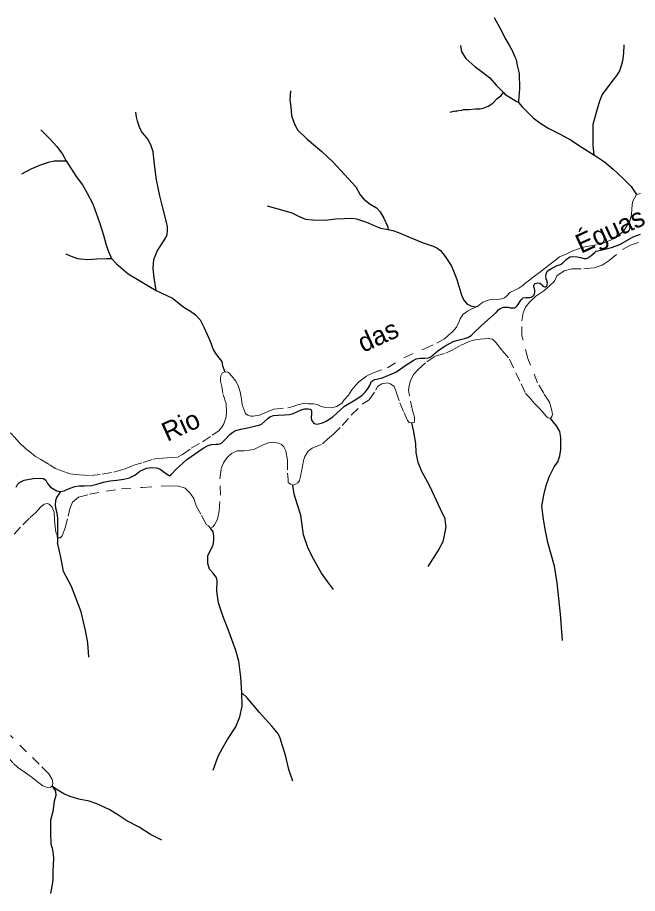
# Model space of a CAD drawing. Extents: x 391.8 to 446, y 8452 to 8507.5.
# Drawn here: x 398.8 to 405.31, y 8490.84 to 8500.03 of the extents above; entities that cross this region are included whole.
import ezdxf
from ezdxf.enums import TextEntityAlignment as Align

# ---------------------------------------------------------------- set-up
doc = ezdxf.new("R2010")
doc.units = 0
doc.header["$LTSCALE"] = 0.064
doc.linetypes.add('LONG_DASHED', pattern=[7.5, 6, -1.5])
doc.linetypes.add('SHORT_DASHED', pattern=[2.7, 1.5, -1.2])
for name, color, linetype, lineweight in [('21', 7, 'SHORT_DASHED', 13), ('7', 7, 'Continuous', 25), ('9', 7, 'LONG_DASHED', 25)]:
    doc.layers.add(name, color=color, linetype=linetype, lineweight=lineweight)
doc.layers.add('61', color=7, linetype='Continuous')

msp = doc.modelspace()

# ---------------------------------------------------------------- linework, layer by layer
at = {"layer": '21'}
for points in [[(405.2964, 8498.1764), (405.3393, 8498.1894)], [(405.2249, 8497.8981), (405.2433, 8497.9719), (405.247, 8498.0198), (405.2507, 8498.0714), (405.2581, 8498.1083), (405.2729, 8498.1378), (405.2964, 8498.1764)], [(403.6289, 8497.0059), (403.6827, 8497.0475), (403.7393, 8497.067), (403.7873, 8497.078), (403.8353, 8497.0744), (403.8796, 8497.0817), (403.9091, 8497.0928), (403.9313, 8497.1112), (403.9645, 8497.1481), (404.0199, 8497.1739), (404.0605, 8497.196), (404.1011, 8497.2218), (404.1233, 8497.244), (404.1602, 8497.2698), (404.2119, 8497.3103), (404.2783, 8497.3583), (404.3411, 8497.4062), (404.3891, 8497.4468), (404.4481, 8497.491), (404.4888, 8497.5242), (404.5515, 8497.5463), (404.6106, 8497.5795), (404.7191, 8497.6216), (404.7744, 8497.6327), (404.8889, 8497.6511), (404.9849, 8497.6806), (405.0809, 8497.7248), (405.1252, 8497.7617), (405.1658, 8497.8023), (405.1916, 8497.8428), (405.2249, 8497.8981)], [(404.3943, 8495.8284), (404.3998, 8495.8383), (404.4088, 8495.8534), (404.4149, 8495.8685), (404.4058, 8495.9107), (404.3817, 8495.9981), (404.3213, 8496.0915), (404.2579, 8496.2), (404.1564, 8496.4554), (404.0921, 8496.693), (404.0921, 8496.8535), (404.1049, 8496.9369), (404.1306, 8496.9947), (404.1756, 8497.0525), (404.2399, 8497.1103), (404.3235, 8497.1681), (404.3813, 8497.2194), (404.4351, 8497.2677), (404.4608, 8497.3255), (404.5379, 8497.3769), (404.6151, 8497.3961), (404.7436, 8497.3961), (404.8529, 8497.409), (404.9365, 8497.4347), (405.0072, 8497.486), (405.1486, 8497.6016), (405.2322, 8497.6465), (405.3157, 8497.6722)], [(400.973, 8496.3154), (401.0059, 8496.3122), (401.0244, 8496.2975), (401.0429, 8496.2754), (401.0909, 8496.2201), (401.113, 8496.1721), (401.1352, 8496.1058), (401.1499, 8496.0283), (401.1573, 8495.9693), (401.1758, 8495.914), (401.1905, 8495.8808), (401.2164, 8495.8624), (401.2459, 8495.8513), (401.2718, 8495.8513), (401.3382, 8495.8624), (401.3936, 8495.8882), (401.4896, 8495.9251), (401.6336, 8495.9398), (401.691, 8495.9545), (401.7464, 8495.9729), (401.7981, 8495.984), (401.8498, 8495.9803), (401.9052, 8495.9803), (401.9421, 8495.9729), (401.979, 8495.9582), (402.0122, 8495.9471), (402.0787, 8495.9398), (402.1082, 8495.9435), (402.1488, 8495.9545), (402.2042, 8495.9914), (402.2264, 8496.0246), (402.2707, 8496.0725), (402.3076, 8496.1278), (402.3408, 8496.1684), (402.3814, 8496.2126), (402.4663, 8496.2753), (402.5254, 8496.3011), (402.6805, 8496.3601), (402.8594, 8496.4686), (403.0699, 8496.5571), (403.1991, 8496.6161), (403.2803, 8496.664), (403.3172, 8496.6972), (403.3689, 8496.7414), (403.4059, 8496.7857), (403.4317, 8496.8373), (403.4428, 8496.8742), (403.4723, 8496.9184), (403.5203, 8496.9516), (403.5609, 8496.9737), (403.6289, 8497.0059)], [(402.9374, 8495.7801), (402.961, 8495.785), (402.9662, 8495.8008), (402.9662, 8495.8404), (402.9425, 8495.9117), (402.9134, 8496.0621), (402.9028, 8496.1228), (402.9081, 8496.1703), (402.9213, 8496.2152), (402.9543, 8496.2885), (403.0057, 8496.3463), (403.0957, 8496.4233), (403.1857, 8496.4811), (403.295, 8496.5132), (403.3592, 8496.5453), (403.4557, 8496.5967), (403.5392, 8496.6352), (403.5842, 8496.648), (403.6549, 8496.6609), (403.7385, 8496.6673), (403.7835, 8496.6609), (403.8221, 8496.6224), (403.8864, 8496.5389), (403.9635, 8496.449), (404.0278, 8496.3078), (404.0856, 8496.1922), (404.1306, 8496.0895), (404.1756, 8496.0446), (404.2206, 8495.9868), (404.2656, 8495.9418), (404.3171, 8495.8905), (404.3424, 8495.8534), (404.3605, 8495.8383), (404.3943, 8495.8284)], [(400.7391, 8495.5808), (400.8425, 8495.6509), (400.9126, 8495.6988), (400.9422, 8495.7357), (400.9643, 8495.7725), (400.9865, 8495.8463), (400.9901, 8495.8979), (400.9865, 8495.9827), (400.9532, 8496.0896), (400.9432, 8496.1611), (400.9284, 8496.2201), (400.9284, 8496.2532), (400.9321, 8496.2754), (400.9469, 8496.3012), (400.973, 8496.3154)], [(401.6869, 8495.1278), (401.7157, 8495.1373), (401.74, 8495.1534), (401.7588, 8495.1776), (401.7696, 8495.218), (401.7777, 8495.2745), (401.7885, 8495.3229), (401.7992, 8495.3848), (401.8127, 8495.4279), (401.8504, 8495.4844), (401.8908, 8495.5167), (401.9996, 8495.5602), (402.051, 8495.6116), (402.1153, 8495.6629), (402.2053, 8495.7528), (402.3017, 8495.862), (402.4174, 8495.9775), (402.4881, 8496.0225), (402.5588, 8496.1252), (402.5781, 8496.1637), (402.6231, 8496.1894), (402.681, 8496.2022), (402.7131, 8496.1894), (402.7517, 8496.1637), (402.771, 8496.1059), (402.8095, 8495.9904), (402.8579, 8495.8853), (402.8922, 8495.8061), (402.9081, 8495.785), (402.9374, 8495.7801)], [(398.658, 8495.6998), (398.681, 8495.6905), (398.7032, 8495.6868), (398.7327, 8495.6647), (398.7659, 8495.6315), (398.8176, 8495.5725), (398.8804, 8495.5135), (398.9431, 8495.4619), (398.9874, 8495.4287), (399.0428, 8495.3955), (399.1351, 8495.3402), (399.1942, 8495.3033), (399.2533, 8495.2812), (399.3456, 8495.248), (399.4526, 8495.237), (399.5671, 8495.2296), (399.6869, 8495.2416), (399.8087, 8495.2637), (399.9084, 8495.2932), (400.0081, 8495.3338), (400.1152, 8495.3669), (400.2222, 8495.4001), (400.2665, 8495.4075)], [(400.2665, 8495.4075), (400.3219, 8495.4112), (400.4142, 8495.4186), (400.477, 8495.4223), (400.5287, 8495.4481), (400.621, 8495.5144), (400.7391, 8495.5808)], [(400.8231, 8494.6778), (400.8479, 8494.6912), (400.8649, 8494.7116), (400.8956, 8494.7695), (400.9127, 8494.8581), (400.9297, 8495.0215), (400.9229, 8495.1952), (400.9365, 8495.3042), (400.9604, 8495.3621), (400.9979, 8495.4166), (401.0423, 8495.4609), (401.1036, 8495.4881), (401.1767, 8495.4896), (401.2282, 8495.496), (401.2796, 8495.5024), (401.3696, 8495.5474), (401.4274, 8495.5731), (401.4724, 8495.5795), (401.5367, 8495.5666)], [(401.5367, 8495.5666), (401.5689, 8495.5538), (401.5946, 8495.5281), (401.6139, 8495.4896), (401.6331, 8495.3869), (401.6331, 8495.2521), (401.6376, 8495.1857)], [(401.6376, 8495.1857), (401.6403, 8495.1534), (401.6484, 8495.148), (401.6618, 8495.1373), (401.6726, 8495.1346), (401.6869, 8495.1278)], [(399.2168, 8494.5807), (399.2261, 8494.576), (399.2454, 8494.576), (399.2647, 8494.5953), (399.2968, 8494.6787), (399.3291, 8494.801), (399.3483, 8494.8781), (399.3741, 8494.9487), (399.4383, 8495.0001), (399.554, 8495.0322), (399.7276, 8495.0643), (399.8883, 8495.0899), (400.1069, 8495.1028), (400.4026, 8495.122), (400.4926, 8495.1156), (400.5569, 8495.0964), (400.6083, 8495.045), (400.6469, 8494.9872), (400.6726, 8494.9102), (400.7285, 8494.8104), (400.7626, 8494.7457), (400.7763, 8494.715), (400.8035, 8494.7014), (400.8231, 8494.6778)], [(398.7627, 8494.6121), (398.8532, 8494.711), (398.9303, 8494.788), (398.9946, 8494.8458), (399.0396, 8494.8971), (399.0782, 8494.9292), (399.1103, 8494.9357), (399.1296, 8494.9292), (399.1617, 8494.8971), (399.181, 8494.8458), (399.1874, 8494.7623), (399.1939, 8494.6917), (399.2004, 8494.6338), (399.2133, 8494.6017), (399.2133, 8494.5824), (399.2168, 8494.5807)], [(398.5354, 8492.5364), (398.5676, 8492.4593), (398.6254, 8492.363), (398.6833, 8492.2924), (398.754, 8492.209), (398.799, 8492.1704), (398.8674, 8492.1185), (398.9498, 8492.0613), (399.0071, 8492.0148), (399.0644, 8491.9719), (399.1109, 8491.954), (399.1431, 8491.9576), (399.1605, 8491.9698)], [(399.1605, 8491.9698), (399.1682, 8492.0005), (399.1611, 8492.0398), (399.1252, 8492.1006), (399.025, 8492.2007), (398.8925, 8492.3295), (398.7242, 8492.5011)]]:
    msp.add_lwpolyline(points, dxfattribs=at)
at = {"layer": '7'}
for points in [[(403.9478, 8496.9943), (403.9694, 8496.9871), (404.0006, 8496.9895), (404.015, 8496.9895), (404.0294, 8496.9943), (404.0438, 8497.0086), (404.0702, 8497.0494), (404.0846, 8497.0709), (404.1062, 8497.0925), (404.1326, 8497.0973), (404.1782, 8497.0973), (404.1902, 8497.0997), (404.1998, 8497.1069), (404.2118, 8497.1141), (404.2214, 8497.1261), (404.2286, 8497.1476), (404.2286, 8497.174), (404.2262, 8497.1884), (404.2166, 8497.21), (404.2166, 8497.2219), (404.2214, 8497.2339), (404.231, 8497.2435), (404.2454, 8497.2483), (404.2598, 8497.2507), (404.2814, 8497.2483), (404.2958, 8497.2363), (404.3054, 8497.2243), (404.3126, 8497.2147), (404.3294, 8497.2076), (404.3414, 8497.2076), (404.3534, 8497.2171), (404.3582, 8497.2291), (404.3606, 8497.2507), (404.3558, 8497.2747), (404.3486, 8497.2938), (404.3438, 8497.3202), (404.3462, 8497.3418), (404.3534, 8497.3609), (404.363, 8497.3753), (404.4038, 8497.4017), (404.4623, 8497.4321), (404.4983, 8497.4441), (404.5175, 8497.4561), (404.5367, 8497.4728), (404.5559, 8497.4944), (404.5943, 8497.5232), (404.6231, 8497.5256), (404.6711, 8497.5232), (404.7071, 8497.516), (404.7455, 8497.5064), (404.7719, 8497.5064), (404.7863, 8497.5112), (404.8151, 8497.5328), (404.8583, 8497.5687), (404.8733, 8497.5812), (404.8901, 8497.586), (404.9621, 8497.6028), (405.0341, 8497.6195), (405.1205, 8497.6531), (405.2596, 8497.7322), (405.3364, 8497.7609)], [(403.6036, 8496.7393), (403.7044, 8496.8351), (403.822, 8496.9406), (403.847, 8496.9679), (403.8638, 8496.9823), (403.8998, 8496.9943), (403.9478, 8496.9943)], [(399.2486, 8495.0603), (399.2871, 8495.0667), (399.3341, 8495.0884), (399.3991, 8495.1136), (399.4461, 8495.1209), (399.5003, 8495.1209), (399.5726, 8495.1245), (399.6304, 8495.1389), (399.6991, 8495.1606), (399.7714, 8495.1714), (399.8401, 8495.1786), (399.9123, 8495.1894), (399.9738, 8495.2039), (400.028, 8495.2328), (400.0822, 8495.2761), (400.1509, 8495.3049), (400.2087, 8495.3122), (400.2529, 8495.3086), (400.2709, 8495.305), (400.2962, 8495.2941), (400.336, 8495.2653), (400.3721, 8495.24), (400.3902, 8495.2292), (400.4046, 8495.2292), (400.4155, 8495.2436), (400.4589, 8495.2905), (400.5745, 8495.3952), (400.748, 8495.5143), (400.7996, 8495.5444), (400.8337, 8495.5553), (400.8817, 8495.5577), (400.9033, 8495.5577), (400.9225, 8495.5601), (400.9392, 8495.5697), (400.9752, 8495.6032), (401.028, 8495.6583), (401.0592, 8495.6847), (401.0904, 8495.7015), (401.1432, 8495.7159), (401.2296, 8495.7326), (401.2992, 8495.7494), (401.3352, 8495.7566), (401.3592, 8495.7686), (401.3904, 8495.7973), (401.424, 8495.8285), (401.4456, 8495.8429), (401.484, 8495.8597), (401.5344, 8495.8621), (401.5992, 8495.8668), (401.6496, 8495.8692), (401.6832, 8495.8764), (401.7312, 8495.898), (401.7743, 8495.9172), (401.8127, 8495.9292), (401.8487, 8495.9268), (401.8703, 8495.9244), (401.8799, 8495.9172), (401.8847, 8495.9004), (401.8847, 8495.8764), (401.8799, 8495.8381), (401.8839, 8495.8097), (401.8935, 8495.7953), (401.9055, 8495.7809), (401.9151, 8495.7737), (401.9319, 8495.7689), (401.9583, 8495.7713), (401.9991, 8495.7833), (402.0375, 8495.7977), (402.1071, 8495.8456), (402.2318, 8495.9559), (402.359, 8496.035), (402.4166, 8496.0709), (402.4478, 8496.1021), (402.4718, 8496.1356), (402.4958, 8496.174), (402.511, 8496.2108), (402.5278, 8496.2252), (402.5494, 8496.2347), (402.619, 8496.2491), (402.7678, 8496.3138), (402.8757, 8496.3857), (402.9509, 8496.4349), (402.9821, 8496.4541), (403.0229, 8496.4589), (403.0733, 8496.4589), (403.1116, 8496.4637), (403.138, 8496.4756), (403.21, 8496.5356), (403.2772, 8496.5835), (403.3708, 8496.6338), (403.4188, 8496.6506), (403.4884, 8496.665), (403.5244, 8496.677), (403.5604, 8496.6985), (403.6036, 8496.7393)], [(398.7831, 8495.1059), (398.7976, 8495.1347), (398.8193, 8495.1564), (398.8663, 8495.1817), (398.9602, 8495.1961), (399.0397, 8495.1997), (399.0686, 8495.1961), (399.0939, 8495.1817), (399.112, 8495.1456), (399.1445, 8495.1059), (399.2096, 8495.0698), (399.2437, 8495.0595), (399.2486, 8495.0603)], [(399.2486, 8495.0603), (399.2241, 8495.021), (399.2079, 8494.9967), (399.197, 8494.9616), (399.1916, 8494.9211), (399.197, 8494.8887), (399.2106, 8494.8374), (399.2187, 8494.778), (399.2187, 8494.6997), (399.2168, 8494.5807), (399.2159, 8494.5252)]]:
    msp.add_lwpolyline(points, dxfattribs=at)
at = {"layer": '9'}
for points in [[(403.8017, 8500.0341), (403.8596, 8499.926), (403.9239, 8499.8036), (403.9578, 8499.745), (403.9946, 8499.6807), (404.0189, 8499.6199), (404.0312, 8499.5924), (404.0435, 8499.5312), (404.0649, 8499.4454), (404.068, 8499.2863), (404.0619, 8499.2036), (404.0586, 8499.1637), (404.0574, 8499.142)], [(405.1636, 8499.7474), (405.1605, 8499.6586), (405.1483, 8499.579), (405.136, 8499.527), (405.1176, 8499.475), (405.09, 8499.4291), (405.0379, 8499.3617), (404.9368, 8499.227), (404.9061, 8499.1566), (404.8785, 8499.0617), (404.8567, 8498.986), (404.8377, 8498.9119), (404.8384, 8498.7862), (404.8384, 8498.6924), (404.8465, 8498.5947)], [(403.4465, 8499.7412), (403.4579, 8499.6755), (403.5047, 8499.6054), (403.5974, 8499.5191), (403.6772, 8499.4618), (403.7573, 8499.4023), (403.8236, 8499.3244), (403.8985, 8499.2464)], [(401.6623, 8499.2635), (401.6571, 8499.1707), (401.6675, 8499.0985), (401.6726, 8499.0056), (401.683, 8498.9746), (401.7088, 8498.9076), (401.7398, 8498.8508), (401.8379, 8498.758), (401.9929, 8498.629), (402.1066, 8498.5207), (402.2305, 8498.3865), (402.3493, 8498.2575), (402.3957, 8498.1739), (402.4339, 8498.1294), (402.4991, 8498.077), (402.5677, 8498.0365), (402.6047, 8497.9958), (402.6442, 8497.9283), (402.6799, 8497.8448), (402.6903, 8497.8087)], [(403.3412, 8499.0414), (403.3853, 8499.0541), (403.4023, 8499.049), (403.4107, 8499.054), (403.4302, 8499.0599), (403.4626, 8499.0624), (403.4799, 8499.0694), (403.5392, 8499.0707), (403.6043, 8499.0757), (403.6494, 8499.0774), (403.6844, 8499.0824), (403.7395, 8499.1024), (403.7879, 8499.134), (403.828, 8499.1807), (403.8697, 8499.2141), (403.8985, 8499.2463), (403.8985, 8499.2464)], [(403.8985, 8499.2464), (403.9133, 8499.231), (404.0334, 8499.1562), (404.0574, 8499.142)], [(404.0574, 8499.142), (404.0965, 8499.0986), (404.1589, 8499.0324), (404.2114, 8498.9827), (404.2809, 8498.928), (404.3741, 8498.8689), (404.4939, 8498.8113), (404.604, 8498.7501), (404.7253, 8498.6704), (404.8465, 8498.5947)], [(400.2536, 8497.1702), (400.2317, 8497.3013), (400.223, 8497.4018), (400.2273, 8497.4936), (400.2622, 8497.5828), (400.3498, 8497.7183), (400.3673, 8497.7576), (400.3716, 8497.8013), (400.3716, 8497.8363), (400.3629, 8497.8887), (400.3279, 8498.0242), (400.2929, 8498.1641), (400.2579, 8498.3301), (400.2357, 8498.4927), (400.2226, 8498.6238), (400.2007, 8498.6893), (400.1701, 8498.7549), (400.1001, 8498.8379), (400.0779, 8498.8834), (400.056, 8498.9484), (400.0461, 8498.9877), (400.0401, 8499.0422)], [(399.0411, 8498.8549), (399.1286, 8498.7675), (399.2117, 8498.6801), (399.2686, 8498.6015), (399.3074, 8498.5301)], [(404.8465, 8498.5947), (404.8554, 8498.5892), (404.9589, 8498.5212), (405.0513, 8498.4441), (405.1509, 8498.3485), (405.2389, 8498.2606), (405.2964, 8498.1764)], [(398.8436, 8498.3946), (398.9399, 8498.4471), (399.0493, 8498.4908), (399.1237, 8498.517), (399.1805, 8498.5301), (399.3074, 8498.5301)], [(399.3074, 8498.5301), (399.413, 8498.3655), (399.4787, 8498.2781), (399.5284, 8498.1901), (399.5884, 8498.0776), (399.6581, 8497.8847), (399.7018, 8497.751), (399.7236, 8497.6592), (399.7499, 8497.5849), (399.7844, 8497.5075)], [(401.4178, 8498.0575), (401.5929, 8498.0105), (401.676, 8497.9858), (401.7052, 8497.9723), (401.7411, 8497.9522), (401.7792, 8497.9342), (401.8196, 8497.9185), (401.896, 8497.9118), (402.0284, 8497.9096), (402.1384, 8497.9208), (402.2259, 8497.9253), (402.309, 8497.9275), (402.3561, 8497.9208), (402.4616, 8497.8872), (402.5424, 8497.8513), (402.6075, 8497.8244), (402.6903, 8497.8087)], [(402.6903, 8497.8087), (402.7365, 8497.7998), (402.7971, 8497.7796), (402.8937, 8497.737), (403.0553, 8497.6698), (403.1608, 8497.6361), (403.1989, 8497.6182), (403.2371, 8497.5891), (403.2865, 8497.5263), (403.3503, 8497.4311), (403.375, 8497.3751), (403.4087, 8497.2854), (403.4401, 8497.1801), (403.4606, 8497.1113), (403.4852, 8497.0665), (403.5144, 8497.0306), (403.5571, 8497.0082), (403.602, 8496.9992), (403.6289, 8497.0059)], [(399.3031, 8497.5555), (399.36, 8497.5293), (399.4256, 8497.5075), (399.5306, 8497.4943), (399.6313, 8497.5031), (399.7319, 8497.5075), (399.7844, 8497.5075)], [(399.7844, 8497.5075), (399.8374, 8497.4494), (399.96, 8497.3446), (400.1044, 8497.2572), (400.1919, 8497.2047), (400.2536, 8497.1702)], [(400.2536, 8497.1702), (400.4238, 8497.0911), (400.542, 8496.9949), (400.6142, 8496.9534), (400.6667, 8496.9141), (400.7148, 8496.8617), (400.7586, 8496.7786), (400.8198, 8496.6388), (400.8505, 8496.5514), (400.8767, 8496.5077), (400.9117, 8496.464), (400.9424, 8496.4246), (400.9511, 8496.3809), (400.973, 8496.3154)], [(404.5196, 8493.4994), (404.4988, 8493.7746), (404.4612, 8494.104), (404.4361, 8494.2792), (404.3652, 8494.5252), (404.3359, 8494.667), (404.3192, 8494.7712), (404.3025, 8494.9088), (404.3233, 8495.0236), (404.3483, 8495.1237), (404.3776, 8495.2154), (404.4319, 8495.3197), (404.4694, 8495.3739), (404.4903, 8495.4364), (404.5028, 8495.5031), (404.5028, 8495.5782), (404.5028, 8495.6282), (404.4903, 8495.6908), (404.4569, 8495.7491), (404.3943, 8495.8284)], [(403.1084, 8494.2748), (403.2126, 8494.4372), (403.2668, 8494.537), (403.2793, 8494.5995), (403.2959, 8494.6952), (403.2918, 8494.7327), (403.2876, 8494.7743), (403.2418, 8494.87), (403.1251, 8495.1156), (403.0417, 8495.2696), (403.0042, 8495.3653), (402.9834, 8495.4694), (402.9792, 8495.5651), (402.9541, 8495.7051), (402.9374, 8495.7801)], [(402.1145, 8494.0324), (402.0534, 8494.1177), (401.9883, 8494.2031), (401.9069, 8494.3494), (401.8499, 8494.4632), (401.8011, 8494.6055), (401.7726, 8494.8128), (401.7319, 8494.9307), (401.7034, 8495.0323), (401.6869, 8495.1278)], [(401.1522, 8492.9481), (401.1434, 8493.1121), (401.1212, 8493.2805), (401.0901, 8493.3913), (401.0184, 8493.5843), (400.9519, 8493.7572), (400.9075, 8493.8946), (400.8897, 8494.0143), (400.8941, 8494.1238), (400.8853, 8494.1592), (400.8675, 8494.1814), (400.8498, 8494.2036), (400.8143, 8494.2479), (400.7965, 8494.3055), (400.7965, 8494.3897), (400.8231, 8494.4429), (400.8498, 8494.5005), (400.8586, 8494.5493), (400.8586, 8494.5936), (400.8498, 8494.6379), (400.8231, 8494.6778)], [(399.5478, 8493.3238), (399.536, 8493.4717), (399.5123, 8493.6019), (399.4648, 8493.7973), (399.3641, 8494.0636), (399.2811, 8494.2234), (399.2515, 8494.3714), (399.2159, 8494.5252)], [(400.8505, 8492.137), (400.9037, 8492.2833), (400.9481, 8492.3675), (401.0013, 8492.4606), (401.0901, 8492.5935), (401.13, 8492.6955), (401.1567, 8492.8107), (401.1522, 8492.9481)], [(401.6892, 8492.0218), (401.6448, 8492.1459), (401.6093, 8492.2966), (401.5783, 8492.3941), (401.5561, 8492.4739), (401.5383, 8492.5138), (401.4673, 8492.598), (401.3386, 8492.7442), (401.2099, 8492.8949), (401.1522, 8492.9481)], [(399.1605, 8491.9698), (399.1946, 8491.9182), (399.1991, 8491.8734), (399.1823, 8491.8133), (399.1678, 8491.7055), (399.1432, 8491.6115), (399.1432, 8491.5332), (399.1432, 8491.4772), (399.1477, 8491.3653), (399.166, 8491.3061), (399.1749, 8491.2188), (399.17, 8491.137), (399.1678, 8491.0832), (399.1678, 8490.9959), (399.1633, 8490.9579), (399.1432, 8490.8437)], [(400.3141, 8491.4025), (400.1952, 8491.4641), (400.0763, 8491.5388), (399.9443, 8491.6048), (399.8386, 8491.6752), (399.7593, 8491.7235), (399.6316, 8491.7851), (399.548, 8491.8115), (399.4423, 8491.8335), (399.3498, 8491.8598), (399.2838, 8491.8906), (399.2045, 8491.939), (399.1605, 8491.9698)]]:
    msp.add_lwpolyline(points, dxfattribs=at)

# ---------------------------------------------------------------- texts
at = {"layer": '61'}
msp.add_text('Rio                         das                            Éguas         ou                        Corrente', height=0.2, rotation=24.434, dxfattribs=at).set_placement((404.6121, 8497.5086), align=Align.CENTER)

doc.saveas('drawing.dxf')
